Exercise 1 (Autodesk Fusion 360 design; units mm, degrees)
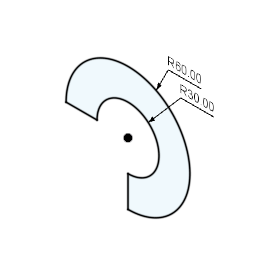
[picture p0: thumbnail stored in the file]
sketch "Sketch1" plane through (0, 0, 0) normal (0, 1, 0) x axis (1, 0, 0)
  line L1 (-60, 0) -> (-30, 0)
  line L2 (0, 60) -> (0, 30)
  arc A1 centre (0, 0) radius 30 clockwise from (0, 30) to (-30, 0)
  arc A2 centre (0, 0) radius 60 clockwise from (0, 60) to (-60, 0)
  point P1 (0, 0)
  point P2 (0, 0)
  point P3 (0, 0)
  point P4 (-30, 0)
  point P6 (0, 30)
  coincident P1 P2
  coincident P1 P3
  horizontal L1
  vertical L2
  horizontal P3 P4
  vertical P3 P6
  dimension "d2" radius A2 = 60
  dimension "d3" radius A1 = 30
